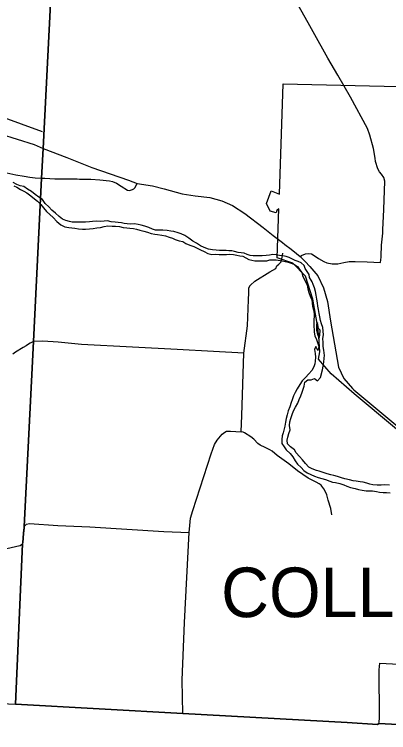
# Model space of a CAD drawing. Extents: x 41.3 to 81.6, y -19.3 to 2.7.
# Drawn here: x 45.839 to 46.925, y -1.085 to 1 of the extents above; entities that cross this region are included whole.
import ezdxf

# ---------------------------------------------------------------- set-up
doc = ezdxf.new("R2010")
doc.units = 0
for name, color, linetype in [('GM_X_Corporation', 7, 'Continuous'), ('GM_X_Major_River', 7, 'Continuous'), ('GM_X_State_Route', 7, 'Continuous'), ('GM_X_Township', 7, 'Continuous'), ('GM_X_Township_Road', 7, 'Continuous'), ('GM_X_Township_Text', 7, 'Continuous')]:
    doc.layers.add(name, color=color, linetype=linetype)

msp = doc.modelspace()

# ---------------------------------------------------------------- linework, layer by layer
at = {"layer": 'GM_X_Corporation'}
msp.add_lwpolyline([(46.584, 0.4876), (46.608, 0.4783), (46.619, 0.799), (47.3288, 0.7822), (47.2918, -0.3441), (47.053, -0.3369), (47.053, -0.2918), (46.8252, -0.1011), (46.7581, -0.0438), (46.7215, -0.0005), (46.7256, 0.0209), (46.722, 0.0646), (46.7171, 0.1029), (46.7053, 0.1736), (46.6837, 0.2398), (46.6465, 0.2782), (46.6014, 0.293), (46.6062, 0.436), (46.6004, 0.4311), (46.5985, 0.4242), (46.5815, 0.4287), (46.5709, 0.4515)], close=True, dxfattribs=at)
at = {"layer": 'GM_X_Major_River'}
for points in [[(46.4887, 0.3089), (46.4781, 0.3118), (46.4698, 0.3137), (46.4614, 0.3141), (46.4534, 0.3144), (46.4428, 0.315), (46.4345, 0.315), (46.4245, 0.3157), (46.4136, 0.317), (46.402, 0.3189), (46.3902, 0.3231), (46.3789, 0.3285), (46.3674, 0.3356), (46.3565, 0.3423), (46.3449, 0.3507), (46.3337, 0.3581), (46.3227, 0.3635), (46.3141, 0.3664), (46.3019, 0.3696), (46.2935, 0.3712), (46.2826, 0.3728), (46.2698, 0.3738), (46.2582, 0.3738), (46.2483, 0.3741), (46.2402, 0.3764), (46.2296, 0.3812), (46.2178, 0.3854), (46.2075, 0.3879), (46.1988, 0.3899), (46.1876, 0.3921), (46.177, 0.3915), (46.1664, 0.3921), (46.158, 0.3928), (46.15, 0.3947), (46.1401, 0.3963), (46.132, 0.3973), (46.1205, 0.3982), (46.1099, 0.4005), (46.0993, 0.3995), (46.0884, 0.3992), (46.0774, 0.3995), (46.0659, 0.3985), (46.0575, 0.3976), (46.0456, 0.3973), (46.0347, 0.3969), (46.0235, 0.3973), (46.0148, 0.3969), (46.0068, 0.3973), (45.9988, 0.3986), (45.9888, 0.4014), (45.9792, 0.4053), (45.9692, 0.4136), (45.9586, 0.423), (45.9477, 0.4316), (45.9394, 0.4419), (45.9291, 0.4515), (45.9205, 0.4624), (45.9099, 0.4692), (45.8993, 0.4772), (45.889, 0.4859), (45.8774, 0.4933), (45.8665, 0.5003), (45.8566, 0.5029), (45.8463, 0.5064), (45.836, 0.5119)], [(45.8383, 0.5023), (45.8466, 0.4987), (45.8569, 0.4923), (45.8672, 0.4868), (45.8758, 0.4817), (45.8867, 0.4734), (45.898, 0.465), (45.9063, 0.4583), (45.9163, 0.448), (45.9237, 0.4384), (45.9326, 0.4284), (45.9426, 0.4191), (45.9519, 0.4101), (45.9628, 0.3986), (45.974, 0.3892), (45.9859, 0.3835), (45.9978, 0.3812), (46.0061, 0.3809), (46.0145, 0.3793), (46.0254, 0.378), (46.0373, 0.3767), (46.0456, 0.3767), (46.0569, 0.378), (46.0681, 0.3786), (46.0784, 0.3802), (46.089, 0.3815), (46.1002, 0.3844), (46.1102, 0.386), (46.1227, 0.3857), (46.133, 0.3851), (46.1442, 0.3844), (46.1551, 0.3815), (46.1654, 0.3806), (46.1744, 0.3796), (46.1853, 0.3786), (46.1933, 0.3767), (46.2036, 0.3738), (46.2149, 0.3706), (46.2251, 0.3683), (46.2357, 0.3645), (46.2463, 0.3619), (46.2547, 0.3616), (46.2669, 0.3594), (46.2775, 0.3571), (46.2887, 0.3533), (46.2977, 0.3504), (46.306, 0.3471), (46.317, 0.3433), (46.3282, 0.3404), (46.3365, 0.3353), (46.3484, 0.3305), (46.36, 0.3263), (46.368, 0.3227), (46.3789, 0.3166), (46.3895, 0.3115), (46.4007, 0.306), (46.4117, 0.3035), (46.4223, 0.3038), (46.4332, 0.3028), (46.4435, 0.3032), (46.4544, 0.3032), (46.4643, 0.3041), (46.4752, 0.3031)], [(46.4752, 0.3031), (46.4842, 0.3008), (46.4929, 0.2989), (46.5017, 0.2979), (46.5105, 0.293), (46.5192, 0.2891), (46.5367, 0.2852), (46.5455, 0.2843), (46.5543, 0.2843), (46.563, 0.2852), (46.5718, 0.2852), (46.5805, 0.2872), (46.5981, 0.2872), (46.6156, 0.2852), (46.6331, 0.2813), (46.6419, 0.2784), (46.6516, 0.2745), (46.6604, 0.2687), (46.6662, 0.2599), (46.673, 0.2512), (46.6749, 0.2424), (46.6788, 0.2336), (46.6839, 0.2246)], [(46.7027, 0.2239), (46.6996, 0.2284), (46.6954, 0.2366), (46.6944, 0.2453), (46.6827, 0.2628), (46.6798, 0.2716), (46.6711, 0.2794), (46.6623, 0.2833), (46.6535, 0.2862), (46.636, 0.294), (46.6273, 0.2969), (46.6175, 0.2989), (46.6078, 0.2998), (46.599, 0.3018), (46.5893, 0.3027), (46.5796, 0.3008), (46.5698, 0.2998), (46.5582, 0.2989), (46.5319, 0.2989), (46.5231, 0.2998), (46.5144, 0.3027), (46.5056, 0.3066), (46.4968, 0.3076), (46.4887, 0.3089)], [(46.6839, 0.2246), (46.6887, 0.2143), (46.6906, 0.2034), (46.6934, 0.1932), (46.6976, 0.1823), (46.7017, 0.172), (46.703, 0.1617), (46.7039, 0.1534), (46.7065, 0.1425), (46.7084, 0.1322), (46.7087, 0.1242), (46.708, 0.1136), (46.7077, 0.103), (46.708, 0.0934), (46.7086, 0.0854), (46.7089, 0.0774), (46.7102, 0.0668), (46.7153, 0.0559), (46.722, 0.0357), (46.7191, 0.0248), (46.714, 0.0357), (46.7098, 0.027), (46.7114, 0.0161), (46.7127, 0.0046), (46.712, -0.0063), (46.7111, -0.0147), (46.7082, -0.0227), (46.7024, -0.0336), (46.6931, -0.0429), (46.6832, -0.0538), (46.6739, -0.064), (46.6672, -0.0743), (46.6592, -0.0867), (46.6537, -0.0973), (46.6492, -0.1076), (46.6451, -0.1185), (46.6419, -0.1265), (46.6377, -0.1387), (46.6338, -0.1512), (46.6306, -0.1621), (46.6277, -0.1727), (46.6252, -0.1836), (46.6235, -0.1954), (46.6213, -0.2034), (46.6184, -0.2143), (46.6162, -0.2236), (46.6145, -0.2342), (46.6145, -0.2451), (46.6222, -0.2554), (46.6276, -0.2641), (46.6388, -0.275), (46.6471, -0.2846), (46.6532, -0.2955), (46.6608, -0.3051), (46.6714, -0.3148), (46.6787, -0.3235), (46.6886, -0.3308), (46.6995, -0.336), (46.7097, -0.3402), (46.7199, -0.3444), (46.7314, -0.3469), (46.7417, -0.3505), (46.7538, -0.3553), (46.7621, -0.3576), (46.7704, -0.3589), (46.7835, -0.3621), (46.7951, -0.3656), (46.8034, -0.3692), (46.8142, -0.373), (46.8273, -0.3763), (46.8372, -0.3792), (46.8475, -0.3814), (46.8596, -0.3827), (46.8689, -0.3827), (46.8775, -0.3827), (46.889, -0.385), (46.898, -0.3869), (46.9085, -0.3879), (46.9188, -0.3876), (46.9287, -0.3892)], [(46.9268, -0.3665), (46.9134, -0.3655), (46.9031, -0.3664), (46.8916, -0.3667), (46.8792, -0.3657), (46.8705, -0.3635), (46.8613, -0.3606), (46.8504, -0.358), (46.8421, -0.357), (46.8306, -0.3551), (46.8219, -0.3535), (46.8111, -0.3515), (46.798, -0.3477), (46.7877, -0.3448), (46.7765, -0.3412), (46.7654, -0.3386), (46.757, -0.3367), (46.7465, -0.3338), (46.735, -0.3299), (46.7235, -0.3261), (46.7152, -0.3241), (46.7033, -0.3193), (46.6931, -0.3139), (46.6832, -0.3036), (46.6746, -0.2933), (46.666, -0.2833), (46.657, -0.2724), (46.6516, -0.2644), (46.6398, -0.2551), (46.6318, -0.2464), (46.6309, -0.2358), (46.6321, -0.2269), (46.635, -0.2166), (46.6389, -0.2063), (46.637, -0.1938), (46.6383, -0.1829), (46.6412, -0.1727), (46.6453, -0.1615), (46.6489, -0.1506), (46.6543, -0.1403), (46.661, -0.1288), (46.6652, -0.1182), (46.67, -0.1076), (46.6742, -0.0961), (46.6793, -0.0794), (46.6819, -0.0679), (46.6899, -0.0608), (46.7001, -0.0605), (46.7097, -0.0564), (46.718, -0.0634), (46.7267, -0.0538), (46.7325, -0.032), (46.7347, -0.0208), (46.7367, -0.0092), (46.738, 0.0017), (46.7383, 0.0097), (46.738, 0.0177), (46.7367, 0.0257), (46.7351, 0.036), (46.7345, 0.0472), (46.7342, 0.0591), (46.7361, 0.0703), (46.7352, 0.0805), (46.7339, 0.0915), (46.7304, 0.1014), (46.7275, 0.1117), (46.7247, 0.1226), (46.7228, 0.1322), (46.7209, 0.1434), (46.7193, 0.1527), (46.718, 0.1633), (46.7161, 0.1739), (46.7145, 0.1848), (46.7126, 0.1954), (46.7101, 0.2063), (46.7062, 0.2159), (46.7027, 0.2239)], [(46.7183, 0.1059), (46.7151, 0.1011), (46.7154, 0.0835), (46.7195, 0.0693), (46.7236, 0.06)], [(46.7236, 0.06), (46.7249, 0.0693), (46.7262, 0.0834), (46.7214, 0.0879), (46.7192, 0.0985), (46.7183, 0.1059)]]:
    msp.add_lwpolyline(points, dxfattribs=at)
at = {"layer": 'GM_X_State_Route'}
for points in [[(46.7771, 0.8237), (46.7485, 0.8728), (46.7062, 0.9494), (46.6917, 0.9757), (46.6364, 1.0746)], [(46.9104, 0.4335), (46.9136, 0.5156), (46.911, 0.527), (46.904, 0.5361), (46.8982, 0.5428), (46.8935, 0.5518), (46.8865, 0.5732), (46.8856, 0.5828), (46.8811, 0.6109), (46.8704, 0.6494), (46.8638, 0.6691), (46.8138, 0.7603), (46.7771, 0.8237)], [(45.7981, 0.6534), (45.8972, 0.6223), (45.9228, 0.6112), (45.9915, 0.5844), (46.0637, 0.5559), (46.1699, 0.519), (46.1958, 0.5091), (46.2398, 0.5021), (46.2742, 0.4939), (46.3263, 0.4797), (46.364, 0.4735), (46.4061, 0.4684), (46.4411, 0.4588), (46.4718, 0.4455), (46.5081, 0.422), (46.5611, 0.3816), (46.5903, 0.3585), (46.617, 0.3377)], [(46.9081, 0.3743), (46.9104, 0.4335)], [(46.903, 0.2984), (46.9041, 0.3299), (46.9078, 0.3651), (46.9081, 0.3743)], [(46.617, 0.3377), (46.6237, 0.3325), (46.642, 0.3184), (46.6575, 0.3059), (46.6678, 0.2974), (46.6828, 0.2828), (46.6964, 0.268), (46.7081, 0.2546), (46.719, 0.2408), (46.7356, 0.2063), (46.7473, 0.1664), (46.7565, 0.1099), (46.779, -0.0242), (46.7948, -0.0569), (46.8196, -0.0857)], [(46.6678, 0.2974), (46.672, 0.2999), (46.6839, 0.3052), (46.6937, 0.3063), (46.7014, 0.305), (46.7092, 0.3001), (46.7217, 0.2911), (46.7363, 0.2826), (46.745, 0.279), (46.7614, 0.2763), (46.7771, 0.2765), (46.795, 0.2801), (46.8104, 0.2828), (46.8184, 0.2829)], [(46.8184, 0.2829), (46.8278, 0.2831), (46.8628, 0.2815), (46.9014, 0.28), (46.9029, 0.2957), (46.903, 0.2984)], [(46.8196, -0.0857), (46.8201, -0.0863), (46.824, -0.0896), (47.0441, -0.2738), (47.2355, -0.4341)]]:
    msp.add_lwpolyline(points, dxfattribs=at)
at = {"layer": 'GM_X_Township'}
for points in [[(44.1816, 1.2065), (44.7642, 1.1774), (45.083, 1.1614), (45.1156, 1.1595), (45.1332, 1.1586), (45.1439, 1.1572), (45.1704, 1.1555), (45.9476, 1.1106), (45.9447, 1.0518), (45.9228, 0.6112), (45.9185, 0.5251), (45.8949, 0.0505), (45.8682, -0.4861), (45.8674, -0.4918), (45.8654, -0.5072), (45.8638, -0.5331), (45.8627, -0.5366), (45.8423, -1.0023), (46.3278, -1.0295), (46.8046, -1.0557), (46.892, -1.0615), (46.8967, -1.0581), (47.3982, -1.085)], [(47.3982, -1.085), (46.8967, -1.0581), (46.892, -1.0615), (46.8046, -1.0557), (46.3278, -1.0295), (45.8423, -1.0023), (45.8627, -0.5366), (45.8638, -0.5331), (45.8654, -0.5072), (45.8674, -0.4918), (45.8682, -0.4861), (45.8949, 0.0505), (45.9185, 0.5251), (45.9228, 0.6112), (45.9447, 1.0518), (45.9476, 1.1106), (46.1745, 1.1003), (46.5449, 1.0858), (46.5758, 1.0845), (46.6145, 1.084), (46.6225, 1.0834), (46.6323, 1.082), (46.9356, 1.0671)]]:
    msp.add_lwpolyline(points, dxfattribs=at)
at = {"layer": 'GM_X_Township_Road'}
for points in [[(45.7158, 0.6801), (45.7193, 0.7125), (45.7203, 0.7245), (45.7248, 0.7287), (45.7315, 0.728), (45.7975, 0.7044), (45.9196, 0.6602)], [(45.8, 0.5445), (45.8434, 0.5345), (45.8679, 0.5309), (45.8838, 0.5272), (45.8998, 0.5262), (45.9185, 0.5251), (45.9279, 0.5245)], [(45.9279, 0.5245), (45.9566, 0.5225), (46.0214, 0.5225), (46.0284, 0.5223)], [(46.0284, 0.5223), (46.0612, 0.5215), (46.0872, 0.52), (46.1156, 0.5166), (46.124, 0.5149), (46.136, 0.5106), (46.1495, 0.5011), (46.1673, 0.4896), (46.1732, 0.4889), (46.1816, 0.4916), (46.1857, 0.4936), (46.1885, 0.4965), (46.1958, 0.5091)], [(46.5239, 0.2145), (46.5363, 0.2256), (46.5797, 0.2533), (46.5974, 0.2627), (46.6008, 0.27), (46.6062, 0.2751), (46.6126, 0.2823), (46.6165, 0.3001), (46.618, 0.3071)], [(46.3278, -1.0295), (46.3257, -0.933), (46.3331, -0.765), (46.3467, -0.5041), (46.3482, -0.4835), (46.3487, -0.473), (46.3501, -0.4624), (46.3567, -0.44), (46.4105, -0.2751), (46.4201, -0.2483), (46.4276, -0.2356), (46.4419, -0.2187), (46.4497, -0.2127), (46.4542, -0.2102), (46.4657, -0.2101), (46.4974, -0.2114), (46.4992, -0.1646), (46.5052, 0.0169), (46.5157, 0.0957), (46.5187, 0.1719), (46.5189, 0.1922), (46.5194, 0.2058), (46.5236, 0.2142), (46.5239, 0.2145)], [(45.8802, 0.0424), (45.8732, 0.038), (45.8646, 0.0333), (45.8425, 0.0195), (45.8346, 0.0139)], [(46.5052, 0.0169), (46.4168, 0.0212), (46.3113, 0.027), (46.1823, 0.034), (46.0342, 0.0423), (45.9663, 0.049), (45.9216, 0.0517), (45.8949, 0.0505), (45.8853, 0.0457), (45.8802, 0.0424)], [(45.07, -0.1631), (45.0738, -0.1644), (45.076, -0.1673), (45.0776, -0.1741), (45.0685, -0.3751), (45.0575, -0.5489), (45.0587, -0.554), (45.0616, -0.5569), (45.0728, -0.5577), (45.2635, -0.5674), (45.3076, -0.5696), (45.3544, -0.5718), (45.4983, -0.5796), (45.5217, -0.5812), (45.5521, -0.5819), (45.5671, -0.5818), (45.5944, -0.5792), (45.72, -0.5689), (45.7338, -0.5671), (45.7701, -0.5608), (45.8549, -0.542)], [(46.5748, -0.2615), (46.5666, -0.2572), (46.5526, -0.2506), (46.545, -0.2453), (46.534, -0.2327), (46.5251, -0.2262), (46.5063, -0.215), (46.5025, -0.2131), (46.4974, -0.2114)], [(46.7603, -0.4527), (46.757, -0.434), (46.7496, -0.4099), (46.7453, -0.3947), (46.7409, -0.3835), (46.7369, -0.377), (46.7312, -0.3695), (46.7287, -0.3669), (46.7236, -0.363), (46.7143, -0.3581), (46.6918, -0.346), (46.6603, -0.3247), (46.6349, -0.3048), (46.6016, -0.2804), (46.5867, -0.2677), (46.5797, -0.2641), (46.5748, -0.2615), (46.5748, -0.2615)], [(45.8668, -0.4965), (45.8674, -0.4918), (45.8682, -0.4861), (45.8748, -0.48), (45.8832, -0.4778), (45.9657, -0.4837), (46.0584, -0.488), (46.2728, -0.5009), (46.3467, -0.5041)], [(45.8549, -0.542), (45.8564, -0.5417), (45.8627, -0.5366), (45.8638, -0.5331), (45.8654, -0.5072), (45.8668, -0.4965)], [(46.8974, -1.0547), (46.8975, -1.054), (46.8978, -1.043), (46.8972, -0.9028), (46.8994, -0.8836), (47.1019, -0.8938), (47.2907, -0.9048), (47.4017, -0.91)], [(45.7183, -0.9968), (45.8423, -1.0023), (46.3278, -1.0295), (46.8046, -1.0557), (46.892, -1.0615), (46.8967, -1.0581), (46.8974, -1.0547)]]:
    msp.add_lwpolyline(points, dxfattribs=at)

# ---------------------------------------------------------------- texts
at = {"layer": 'GM_X_Township_Text'}
msp.add_text('COLLEGE', height=0.144, rotation=0, dxfattribs=at).set_placement((46.4388, -0.7497))

doc.saveas('drawing.dxf')
